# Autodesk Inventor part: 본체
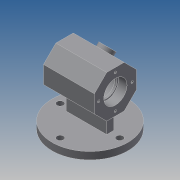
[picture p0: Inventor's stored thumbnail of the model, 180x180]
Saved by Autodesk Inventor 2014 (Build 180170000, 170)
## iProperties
Created: 2021-02
Part Number: 본체
Material: Generic
Document SubType Name: Modeling
Designer: kb542
Density: 1 g/cm^3
Appearance: Default
Author: kb542
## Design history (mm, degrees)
sketch "스케치2" dims "d5" = 58
  geometry: L1 (-12.012, 29)-(12.012, 29); L2 (12.012, 29)-(29, 12.012); L3 (29, 12.012)-(29, -12.012); L4 (29, -12.012)-(12.012, -29); L5 (12.012, -29)-(-12.012, -29); L6 (-12.012, -29)-(-29, -12.012); L7 (-29, -12.012)-(-29, 12.012); L8 (-29, 12.012)-(-12.012, 29); 5 further points
  constraints: 16 end point, 3 coincident, 1 horizontal, 1 midpoint, 20 other
extrude "돌출1" new body sketch "스케치2" stored distance "d6" = 70; taper "d7" = 0 deg
sketch "스케치1"
  geometry: L1 (-35, 0)-(35, 0); L2 (-35, 16)-(-23, 16); L3 (-23, 16)-(-23, 14); L4 (-23, 14)-(-20, 14); L5 (-20, 14)-(-20, 22); L6 (-20, 22)-(20, 22); L7 (20, 22)-(20, 14); L8 (20, 14)-(23, 14); L9 (23, 14)-(23, 16); L10 (23, 16)-(35, 16); L11 (-35, 12.012)-(-35, -12.012) reference; L12 (35, -12.012)-(35, 12.012) reference; L13 (-35, 16)-(-35, 0); L14 (-35, 29)-(-35, 12.012) reference; L15 (35, 0)-(35, 16); L16 (35, 12.012)-(35, 29) reference; 2 further points
  constraints: 24 end point, 5 collinear, 5 parallel, 1 coincident, 1 horizontal, 1 midpoint, 1 perpendicular
  dimensions: "d1" = 40 distance between parallel lines of L7 L5; "d3" = 3 distance between parallel lines of L5 L3; "d4" = 3 distance between parallel lines of L9 L7; "d9" = 44 diameter of L6 L1; "d10" = 32 diameter of L2 L1; "d11" = 28 diameter of L4 L1; "d12" = 32 diameter of L10 L1; "d13" = 28 diameter of L8 L1; "d16" = 12 distance between parallel lines of L3 L13
revolve "회전1" sketch "스케치1" stored, may be unused: angle "d14" = 90 deg
sketch "스케치3" dims "d15" = 46
  geometry: C1 r 16 at (0, 0) reference; 2 further points
  constraints: 2 vertical alignment, 2 other
hole "구멍1" sketch "스케치3" at (0, 23) diameter "d17" = 3.242; stored, may be unused: countersink angle "d21" = 90 deg, drill point angle "d23" = 118 deg; dims "d18" = 8, "d19" = 4, "d20" = 2, "d22" = 10
sketch "스케치4"
  geometry: L1 (0, -24.024)-(0, 0) reference; C1 r 10 at (35, -12.012); 2 further points
  constraints: 1 centre point, 1 horizontal alignment, 1 midpoint
  dimensions: "d27" = 35 distance from line of L1 C1.centre; "d33" = 20 diameter of C1
extrude "돌출2" join sketch "스케치4" distance "d28" = 5; taper "d29" = 0 deg
hole "구멍2" diameter "d37" = 10.917; stored, may be unused: countersink angle "d41" = 90 deg, drill point angle "d43" = 118 deg; dims "d35" = 10, "d36" = 10, "d38" = 6, "d39" = 16, "d40" = 2, "d42" = 8
node "작업 평면1"
sketch "스케치6" dims "d46" = 82
  geometry: C1 r 52 at (0, 0); C2 r 4.5 at (0, 41); C3 r 4.5 at (-41, 0); C4 r 4.5 at (0, -41); C5 r 4.5 at (41, 0); 1 further point
  constraints: 5 centre point, 2 vertical alignment, 1 coincident, 11 other
  dimensions: "d45" = 104 diameter of C1; "d47" = 9 diameter of C2; "d50" = 360 deg dimension on C1.centre C2.centre (derived)
extrude "돌출3" join sketch "스케치6" distance "d52" = 10; taper "d53" = 0 deg
sketch "스케치7"
  geometry: L1 (-28, 5)-(28, 5); L2 (28, 5)-(28, -5); L3 (28, -5)-(-28, -5); L4 (-28, -5)-(-28, 5); C1 r 52 at (0, 0) reference; 2 further points
  constraints: 8 end point, 2 midpoint, 2 parallel, 1 horizontal, 1 horizontal alignment, 1 perpendicular, 1 vertical alignment
  dimensions: "d54" = 10 distance between parallel lines of L3 L1; "d55" = 56 distance between parallel lines of L2 L4
extrude "돌출4" join sketch "스케치7" stored distance "d56" = 10; taper "d57" = 0 deg
node "솔리드1"
pattern_circular "원형 패턴1" dims angle "d25" = 360 deg
mirror "대칭1"
other parameters: "d44" = -62
